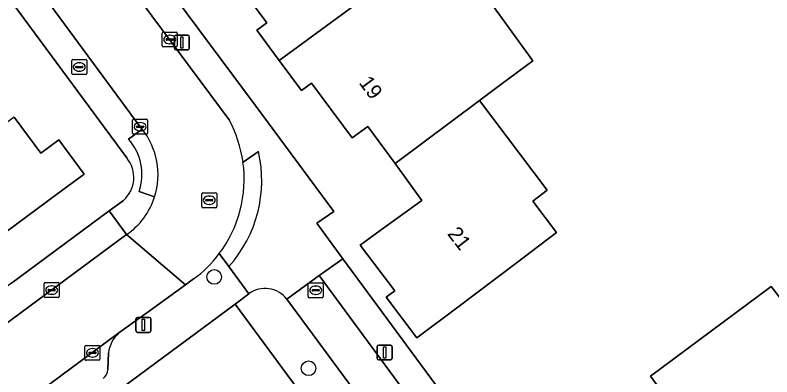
# Model space of a CAD drawing. Extents: x 163426 to 164192, y 380329 to 381641.
# Drawn here: x 163703.9 to 163754.4, y 381322.3 to 381346.5 of the extents above; entities that cross this region are included whole.
import ezdxf

# ---------------------------------------------------------------- set-up
doc = ezdxf.new("R2010")
doc.units = 0
for name, color, linetype in [('IMGEO_Boom', 7, 'Continuous'), ('IMGEO_Brandkraan', 7, 'Continuous'), ('IMGEO_Erf', 7, 'Continuous'), ('IMGEO_Fietspad_open', 7, 'Continuous'), ('IMGEO_Groenvoorziening', 7, 'Continuous'), ('IMGEO_Haag', 7, 'Continuous'), ('IMGEO_Kolk', 7, 'Continuous'), ('IMGEO_Lichtmast', 7, 'Continuous'), ('IMGEO_Pand', 7, 'Continuous'), ('IMGEO_Pand_nummerreeks', 7, 'Continuous'), ('IMGEO_Parkeervlak_open', 7, 'Continuous'), ('IMGEO_Rijbaan_lokaal_open', 7, 'Continuous'), ('IMGEO_Rioolput', 7, 'Continuous'), ('IMGEO_Voetpad_open', 7, 'Continuous')]:
    doc.layers.add(name, color=color, linetype=linetype)

msp = doc.modelspace()

# ---------------------------------------------------------------- linework, layer by layer
at = {"layer": 'IMGEO_Boom'}
for centre in [(163717.207, 381328.972), (163723.509, 381322.873)]:
    msp.add_circle(centre, 0.489, dxfattribs=at)
at = {"layer": 'IMGEO_Brandkraan'}
for p, q in [((163707.695, 381342.565), (163707.695, 381343.417)), ((163707.77, 381343.491), (163708.622, 381343.491)), ((163708.696, 381343.417), (163708.696, 381342.565)), ((163707.954, 381342.985), (163707.954, 381342.997)), ((163708.392, 381342.948), (163707.994, 381342.948)), ((163707.997, 381343.034), (163708.395, 381343.034)), ((163708.183, 381343.271), (163708.208, 381343.271)), ((163708.438, 381342.997), (163708.438, 381342.985)), ((163708.622, 381342.491), (163707.77, 381342.491)), ((163708.206, 381342.711), (163708.181, 381342.711))]:
    msp.add_line(p, q, dxfattribs=at)
for points in [[(163707.695, 381342.565), (163707.695, 381343.417)], [(163707.77, 381343.491), (163708.622, 381343.491)], [(163708.696, 381343.417), (163708.696, 381342.565)], [(163708.622, 381342.491), (163707.77, 381342.491)]]:
    msp.add_lwpolyline(points, dxfattribs=at)
for centre, radius, start, end in [((163707.772, 381343.415), 0.0765, 91.552, 178.448), ((163707.772, 381343.415), 0.0765, 91.552, 178.448), ((163708.62, 381343.415), 0.0765, 1.552, 88.448), ((163708.62, 381343.415), 0.0765, 1.552, 88.448), ((163707.994, 381342.994), 0.0403, 85.8775, 175.7526), ((163707.991, 381342.984), 0.0366, 178.938, 274.7102), ((163708.395, 381342.991), 0.043, 264.8664, 352.4533), ((163708.399, 381342.996), 0.0386, 1.7309, 96.639), ((163707.772, 381342.567), 0.0765, 181.552, 268.448), ((163707.772, 381342.567), 0.0765, 181.552, 268.448), ((163708.62, 381342.567), 0.0765, 271.552, 358.448), ((163708.62, 381342.567), 0.0765, 271.552, 358.448)]:
    msp.add_arc(centre, radius, start, end, dxfattribs=at)
for centre, major_axis, ratio, start_param, end_param in [((163708.182, 381342.991), (-0.387, 0.002), 0.722429, 4.712389, 7.853982), ((163708.207, 381342.991), (-0.39, 0.002), 0.717154, 1.570796, 4.712389)]:
    msp.add_ellipse(centre, major_axis=major_axis, ratio=ratio, start_param=start_param, end_param=end_param, dxfattribs=at)
at = {"layer": 'IMGEO_Erf'}
for points in [[(163711.368, 381336.921), (163689.653, 381366.328)], [(163735.787, 381347.111), (163738.487, 381343.396), (163736.347, 381341.821), (163734.921, 381340.756), (163739.435, 381334.761), (163738.482, 381334.044), (163740.074, 381331.931), (163737.378, 381329.902), (163733.383, 381326.894), (163730.747, 381324.909), (163728.702, 381327.626), (163729.261, 381328.047), (163726.965, 381331.096), (163728.301, 381332.068), (163731.074, 381334.085), (163729.283, 381336.545), (163727.477, 381339.027), (163726.416, 381338.255), (163723.707, 381341.921), (163723.032, 381341.423), (163721.556, 381343.421), (163720.056, 381345.451), (163720.729, 381345.949), (163718.015, 381349.623)], [(163713.908, 381348.57), (163719.936, 381340.439), (163725.188, 381333.354), (163724.056, 381332.559), (163725.803, 381330.185), (163731.664, 381322.22), (163738.793, 381312.532), (163744.754, 381316.918), (163744.079, 381317.837), (163747.519, 381320.368), (163747.706, 381320.506), (163746.336, 381322.354), (163754.409, 381328.33)], [(163754.409, 381328.33), (163756.406, 381325.749), (163759.424, 381327.984), (163761.274, 381334.469), (163761.883, 381334.26), (163762.493, 381334.701), (163765.257, 381330.885), (163769.779, 381334.233), (163768.152, 381336.451), (163770.531, 381341.026), (163772.822, 381337.902), (163777.298, 381341.215), (163776.622, 381342.131), (163780.336, 381344.88), (163784.831, 381348.208)], [(163703.839, 381339.652), (163705.619, 381337.238), (163706.83, 381338.13), (163708.53, 381335.84), (163706.775, 381334.547), (163701.911, 381330.966)], [(163703.68, 381328.564), (163710.193, 381333.382), (163711.148, 381334.089)], [(163740.553, 381295.871), (163741.259, 381296.424), (163738.778, 381299.792), (163718.602, 381327.167), (163657.027, 381281.631)]]:
    msp.add_lwpolyline(points, dxfattribs=at)
msp.add_arc((163709.799, 381335.618), 2.04, 311.4237, 39.6922, dxfattribs=at)
at = {"layer": 'IMGEO_Fietspad_open'}
msp.add_lwpolyline([(163739.99, 381303.177), (163740.117, 381303.002), (163741.174, 381301.544), (163743.348, 381303.104), (163724.224, 381329.071), (163722.053, 381327.501)], close=True, dxfattribs=at)
at = {"layer": 'IMGEO_Groenvoorziening'}
for points in [[(163719.53, 381327.853), (163718.602, 381327.167), (163738.778, 381299.792), (163739.529, 381300.378)], [(163740.117, 381303.002), (163739.99, 381303.177), (163722.053, 381327.501)]]:
    msp.add_lwpolyline(points, dxfattribs=at)
msp.add_arc((163720.61, 381326.375), 1.83, 37.9522, 126.1629, dxfattribs=at)
at = {"layer": 'IMGEO_Haag'}
for points in [[(163719.53, 381327.853), (163718.602, 381327.167), (163738.778, 381299.792), (163739.529, 381300.378)], [(163740.117, 381303.002), (163739.99, 381303.177), (163722.053, 381327.501)]]:
    msp.add_lwpolyline(points, dxfattribs=at)
msp.add_arc((163720.61, 381326.375), 1.83, 37.9522, 126.1629, dxfattribs=at)
at = {"layer": 'IMGEO_Kolk'}
for p, q in [((163713.81, 381345.329), (163714.662, 381345.329)), ((163713.735, 381344.403), (163713.735, 381345.255)), ((163713.994, 381344.823), (163713.994, 381344.835)), ((163714.037, 381344.872), (163714.435, 381344.872)), ((163714.223, 381345.109), (163714.248, 381345.109)), ((163714.478, 381344.835), (163714.478, 381344.823)), ((163714.736, 381345.255), (163714.736, 381344.403)), ((163714.662, 381344.329), (163713.81, 381344.329)), ((163714.432, 381344.786), (163714.034, 381344.786)), ((163714.246, 381344.549), (163714.221, 381344.549)), ((163711.76, 381338.579), (163711.76, 381339.431)), ((163711.835, 381339.505), (163712.687, 381339.505)), ((163712.248, 381339.285), (163712.273, 381339.285)), ((163712.761, 381339.431), (163712.761, 381338.579)), ((163712.019, 381338.999), (163712.019, 381339.011)), ((163712.457, 381338.962), (163712.059, 381338.962)), ((163712.062, 381339.048), (163712.46, 381339.048)), ((163712.503, 381339.011), (163712.503, 381338.999)), ((163712.687, 381338.505), (163711.835, 381338.505)), ((163712.271, 381338.725), (163712.246, 381338.725)), ((163705.852, 381327.671), (163705.852, 381328.523)), ((163705.927, 381328.597), (163706.779, 381328.597)), ((163706.154, 381328.14), (163706.552, 381328.14)), ((163706.34, 381328.377), (163706.365, 381328.377)), ((163706.853, 381328.523), (163706.853, 381327.671)), ((163723.488, 381327.661), (163723.488, 381328.513)), ((163723.563, 381328.587), (163724.415, 381328.587)), ((163723.79, 381328.13), (163724.188, 381328.13)), ((163723.976, 381328.367), (163724.001, 381328.367)), ((163724.489, 381328.513), (163724.489, 381327.661)), ((163706.111, 381328.091), (163706.111, 381328.103)), ((163706.549, 381328.054), (163706.151, 381328.054)), ((163706.363, 381327.817), (163706.338, 381327.817)), ((163706.595, 381328.103), (163706.595, 381328.091)), ((163723.747, 381328.081), (163723.747, 381328.093)), ((163724.185, 381328.044), (163723.787, 381328.044)), ((163723.999, 381327.807), (163723.974, 381327.807)), ((163724.231, 381328.093), (163724.231, 381328.081)), ((163706.779, 381327.597), (163705.927, 381327.597)), ((163724.415, 381327.587), (163723.563, 381327.587)), ((163708.577, 381323.48), (163708.577, 381324.332)), ((163708.652, 381324.406), (163709.504, 381324.406)), ((163709.065, 381324.186), (163709.09, 381324.186)), ((163709.578, 381324.332), (163709.578, 381323.48)), ((163708.836, 381323.9), (163708.836, 381323.912)), ((163709.274, 381323.863), (163708.876, 381323.863)), ((163708.879, 381323.949), (163709.277, 381323.949)), ((163709.088, 381323.626), (163709.063, 381323.626)), ((163709.32, 381323.912), (163709.32, 381323.9)), ((163709.504, 381323.406), (163708.652, 381323.406))]:
    msp.add_line(p, q, dxfattribs=at)
for points in [[(163713.81, 381345.329), (163714.662, 381345.329)], [(163713.735, 381344.403), (163713.735, 381345.255)], [(163714.736, 381345.255), (163714.736, 381344.403)], [(163714.662, 381344.329), (163713.81, 381344.329)], [(163711.76, 381338.579), (163711.76, 381339.431)], [(163711.835, 381339.505), (163712.687, 381339.505)], [(163712.761, 381339.431), (163712.761, 381338.579)], [(163712.687, 381338.505), (163711.835, 381338.505)], [(163705.852, 381327.671), (163705.852, 381328.523)], [(163705.927, 381328.597), (163706.779, 381328.597)], [(163706.853, 381328.523), (163706.853, 381327.671)], [(163723.488, 381327.661), (163723.488, 381328.513)], [(163723.563, 381328.587), (163724.415, 381328.587)], [(163724.489, 381328.513), (163724.489, 381327.661)], [(163706.779, 381327.597), (163705.927, 381327.597)], [(163724.415, 381327.587), (163723.563, 381327.587)], [(163708.577, 381323.48), (163708.577, 381324.332)], [(163708.652, 381324.406), (163709.504, 381324.406)], [(163709.578, 381324.332), (163709.578, 381323.48)], [(163709.504, 381323.406), (163708.652, 381323.406)]]:
    msp.add_lwpolyline(points, dxfattribs=at)
for centre, radius, start, end in [((163713.812, 381345.253), 0.0765, 91.552, 178.448), ((163713.812, 381345.253), 0.0765, 91.552, 178.448), ((163714.66, 381345.253), 0.0765, 1.552, 88.448), ((163714.66, 381345.253), 0.0765, 1.552, 88.448), ((163714.034, 381344.832), 0.0403, 85.8775, 175.7526), ((163714.031, 381344.822), 0.0366, 178.938, 274.7102), ((163714.435, 381344.829), 0.043, 264.8664, 352.4533), ((163714.439, 381344.834), 0.0386, 1.7309, 96.639), ((163713.812, 381344.405), 0.0765, 181.552, 268.448), ((163713.812, 381344.405), 0.0765, 181.552, 268.448), ((163714.66, 381344.405), 0.0765, 271.552, 358.448), ((163714.66, 381344.405), 0.0765, 271.552, 358.448), ((163711.837, 381339.429), 0.0765, 91.552, 178.448), ((163711.837, 381339.429), 0.0765, 91.552, 178.448), ((163712.685, 381339.429), 0.0765, 1.552, 88.448), ((163712.685, 381339.429), 0.0765, 1.552, 88.448), ((163712.059, 381339.008), 0.0403, 85.8775, 175.7526), ((163712.056, 381338.998), 0.0366, 178.938, 274.7102), ((163712.46, 381339.005), 0.043, 264.8664, 352.4533), ((163712.464, 381339.01), 0.0386, 1.7309, 96.639), ((163711.837, 381338.581), 0.0765, 181.552, 268.448), ((163711.837, 381338.581), 0.0765, 181.552, 268.448), ((163712.685, 381338.581), 0.0765, 271.552, 358.448), ((163712.685, 381338.581), 0.0765, 271.552, 358.448), ((163705.929, 381328.521), 0.0765, 91.552, 178.448), ((163705.929, 381328.521), 0.0765, 91.552, 178.448), ((163706.151, 381328.1), 0.0403, 85.8775, 175.7526), ((163706.556, 381328.102), 0.0386, 1.7309, 96.639), ((163706.777, 381328.521), 0.0765, 1.552, 88.448), ((163706.777, 381328.521), 0.0765, 1.552, 88.448), ((163723.565, 381328.511), 0.0765, 91.552, 178.448), ((163723.565, 381328.511), 0.0765, 91.552, 178.448), ((163723.787, 381328.09), 0.0403, 85.8775, 175.7526), ((163724.192, 381328.092), 0.0386, 1.7309, 96.639), ((163724.413, 381328.511), 0.0765, 1.552, 88.448), ((163724.413, 381328.511), 0.0765, 1.552, 88.448), ((163705.929, 381327.673), 0.0765, 181.552, 268.448), ((163705.929, 381327.673), 0.0765, 181.552, 268.448), ((163706.148, 381328.09), 0.0366, 178.938, 274.7102), ((163706.552, 381328.097), 0.043, 264.8664, 352.4533), ((163706.777, 381327.673), 0.0765, 271.552, 358.448), ((163706.777, 381327.673), 0.0765, 271.552, 358.448), ((163723.565, 381327.663), 0.0765, 181.552, 268.448), ((163723.565, 381327.663), 0.0765, 181.552, 268.448), ((163723.784, 381328.08), 0.0366, 178.938, 274.7102), ((163724.188, 381328.087), 0.043, 264.8664, 352.4533), ((163724.413, 381327.663), 0.0765, 271.552, 358.448), ((163724.413, 381327.663), 0.0765, 271.552, 358.448), ((163708.654, 381324.33), 0.0765, 91.552, 178.448), ((163708.654, 381324.33), 0.0765, 91.552, 178.448), ((163709.502, 381324.33), 0.0765, 1.552, 88.448), ((163709.502, 381324.33), 0.0765, 1.552, 88.448), ((163708.876, 381323.909), 0.0403, 85.8775, 175.7526), ((163708.873, 381323.899), 0.0366, 178.938, 274.7102), ((163709.277, 381323.906), 0.043, 264.8664, 352.4533), ((163709.281, 381323.911), 0.0386, 1.7309, 96.639), ((163708.654, 381323.482), 0.0765, 181.552, 268.448), ((163708.654, 381323.482), 0.0765, 181.552, 268.448), ((163709.502, 381323.482), 0.0765, 271.552, 358.448), ((163709.502, 381323.482), 0.0765, 271.552, 358.448)]:
    msp.add_arc(centre, radius, start, end, dxfattribs=at)
for centre, major_axis, ratio, start_param, end_param in [((163714.222, 381344.829), (-0.387, 0.002), 0.722429, 4.712389, 7.853982), ((163714.247, 381344.829), (-0.39, 0.002), 0.717154, 1.570796, 4.712389), ((163712.247, 381339.005), (-0.387, 0.002), 0.722429, 4.712389, 7.853982), ((163712.272, 381339.005), (-0.39, 0.002), 0.717154, 1.570796, 4.712389), ((163706.339, 381328.097), (-0.387, 0.002), 0.722429, 4.712389, 7.853982), ((163706.364, 381328.097), (-0.39, 0.002), 0.717154, 1.570796, 4.712389), ((163723.975, 381328.087), (-0.387, 0.002), 0.722429, 4.712389, 7.853982), ((163724, 381328.087), (-0.39, 0.002), 0.717154, 1.570796, 4.712389), ((163709.064, 381323.906), (-0.387, 0.002), 0.722429, 4.712389, 7.853982), ((163709.089, 381323.906), (-0.39, 0.002), 0.717154, 1.570796, 4.712389)]:
    msp.add_ellipse(centre, major_axis=major_axis, ratio=ratio, start_param=start_param, end_param=end_param, dxfattribs=at)
at = {"layer": 'IMGEO_Lichtmast'}
for p, q in [((163714.551, 381344.228), (163714.551, 381345.028)), ((163714.551, 381345.028), (163714.551, 381344.228)), ((163714.651, 381345.128), (163715.441, 381345.128)), ((163715.441, 381345.128), (163714.651, 381345.128)), ((163715.541, 381345.028), (163715.541, 381344.228)), ((163715.541, 381344.228), (163715.541, 381345.028)), ((163715.441, 381344.128), (163714.651, 381344.128)), ((163714.651, 381344.128), (163715.441, 381344.128)), ((163711.984, 381325.369), (163711.984, 381326.169)), ((163711.984, 381326.169), (163711.984, 381325.369)), ((163712.084, 381326.269), (163712.874, 381326.269)), ((163712.874, 381326.269), (163712.084, 381326.269)), ((163712.974, 381326.169), (163712.974, 381325.369)), ((163712.974, 381325.369), (163712.974, 381326.169)), ((163712.874, 381325.269), (163712.084, 381325.269)), ((163712.084, 381325.269), (163712.874, 381325.269)), ((163728.094, 381323.528), (163728.094, 381324.328)), ((163728.094, 381324.328), (163728.094, 381323.528)), ((163728.194, 381324.428), (163728.984, 381324.428)), ((163728.984, 381324.428), (163728.194, 381324.428)), ((163729.084, 381324.328), (163729.084, 381323.528)), ((163729.084, 381323.528), (163729.084, 381324.328)), ((163728.984, 381323.428), (163728.194, 381323.428)), ((163728.194, 381323.428), (163728.984, 381323.428))]:
    msp.add_line(p, q, dxfattribs=at)
for points in [[(163714.971, 381345.003), (163715.121, 381345.003), (163715.121, 381344.253), (163714.971, 381344.253), (163714.971, 381345.003)], [(163712.404, 381326.144), (163712.554, 381326.144), (163712.554, 381325.394), (163712.404, 381325.394), (163712.404, 381326.144)], [(163728.514, 381324.303), (163728.664, 381324.303), (163728.664, 381323.553), (163728.514, 381323.553), (163728.514, 381324.303)]]:
    msp.add_lwpolyline(points, dxfattribs=at)
for centre, start, end in [((163714.651, 381345.028), 90, 180), ((163714.651, 381345.028), 90, 180), ((163715.441, 381345.028), 0, 90), ((163715.441, 381345.028), 360, 90), ((163714.651, 381344.228), 180, 270), ((163714.651, 381344.228), 180, 270), ((163715.441, 381344.228), 270, 0), ((163715.441, 381344.228), 270, 0), ((163712.084, 381326.169), 90, 180), ((163712.084, 381326.169), 90, 180), ((163712.874, 381326.169), 0, 90), ((163712.874, 381326.169), 360, 90), ((163712.084, 381325.369), 180, 270), ((163712.084, 381325.369), 180, 270), ((163712.874, 381325.369), 270, 0), ((163712.874, 381325.369), 270, 0), ((163728.194, 381324.328), 90, 180), ((163728.194, 381324.328), 90, 180), ((163728.984, 381324.328), 0, 90), ((163728.984, 381324.328), 360, 90), ((163728.194, 381323.528), 180, 270), ((163728.194, 381323.528), 180, 270), ((163728.984, 381323.528), 270, 0), ((163728.984, 381323.528), 270, 0)]:
    msp.add_arc(centre, 0.1, start, end, dxfattribs=at)
at = {"layer": 'IMGEO_Pand'}
for points in [[(163721.556, 381343.421), (163729.777, 381349.473), (163727.101, 381353.026), (163726.346, 381352.457), (163724.754, 381354.571), (163723.991, 381354.011), (163723.636, 381354.492), (163721.821, 381353.159), (163722.175, 381352.677), (163718.015, 381349.623), (163720.729, 381345.949), (163720.056, 381345.451)], [(163735.787, 381347.111), (163732.547, 381351.512), (163729.777, 381349.473), (163721.556, 381343.421), (163723.032, 381341.423), (163723.707, 381341.921), (163726.416, 381338.255), (163727.477, 381339.027), (163729.283, 381336.545), (163734.921, 381340.756), (163736.347, 381341.821), (163738.487, 381343.396)], [(163734.921, 381340.756), (163729.283, 381336.545), (163731.074, 381334.085), (163728.301, 381332.068), (163726.965, 381331.096), (163729.261, 381328.047), (163728.702, 381327.626), (163730.747, 381324.909), (163733.383, 381326.894), (163737.378, 381329.902), (163740.074, 381331.931), (163738.482, 381334.044), (163739.435, 381334.761)], [(163696.592, 381334.313), (163697.097, 381333.631), (163700.07, 381329.61), (163701.911, 381330.966), (163706.775, 381334.547), (163708.53, 381335.84), (163706.83, 381338.13), (163705.619, 381337.238), (163703.839, 381339.652)], [(163756.406, 381325.749), (163754.409, 381328.33), (163746.336, 381322.354), (163747.706, 381320.506), (163753.793, 381312.296), (163755.819, 381313.784), (163755.286, 381314.463), (163758.925, 381317.163), (163758.165, 381318.209), (163760.639, 381320.005)]]:
    msp.add_lwpolyline(points, close=True, dxfattribs=at)
at = {"layer": 'IMGEO_Parkeervlak_open'}
for points in [[(163710.833, 381325.231), (163656.677, 381285.107)], [(163710.107, 381322.8), (163710.147, 381323.915)]]:
    msp.add_lwpolyline(points, dxfattribs=at)
for centre, radius, start, end in [((163712.269, 381323.646), 2.139, 132.1696, 172.7664), ((163709.322, 381322.83), 0.786, 306.6553, 357.7962)]:
    msp.add_arc(centre, radius, start, end, dxfattribs=at)
at = {"layer": 'IMGEO_Rijbaan_lokaal_open'}
for points in [[(163691.302, 381367.414), (163695.359, 381361.911), (163701.623, 381353.484), (163705.653, 381347.998), (163712.258, 381339.005), (163712.395, 381338.84)], [(163718.204, 381339.455), (163712.407, 381347.279)], [(163656.677, 381285.107), (163710.833, 381325.231), (163712.71, 381326.586), (163715.289, 381328.447), (163711.359, 381331.806), (163694.161, 381319.1), (163691.113, 381316.849), (163682.665, 381310.607), (163677.183, 381306.556), (163668.338, 381300.021), (163662.864, 381295.976), (163653.949, 381289.389), (163650.902, 381287.137), (163650.108, 381286.551)], [(163711.359, 381331.806), (163715.289, 381328.447), (163715.832, 381328.839)]]:
    msp.add_lwpolyline(points, dxfattribs=at)
for centre, radius, start, end in [((163710.95, 381335.511), 8.257, 7.8143, 28.5308), ((163708.561, 381335.799), 4.894, 342.3838, 38.4176), ((163710.938, 381335.506), 8.269, 322.9972, 7.842), ((163708.641, 381335.774), 4.81, 304.4097, 342.3778), ((163710.972, 381335.466), 8.218, 306.2522, 323.0738)]:
    msp.add_arc(centre, radius, start, end, dxfattribs=at)
at = {"layer": 'IMGEO_Rioolput'}
for p, q in [((163716.376, 381333.672), (163716.376, 381334.524)), ((163716.451, 381334.598), (163717.303, 381334.598)), ((163716.864, 381334.378), (163716.889, 381334.378)), ((163717.377, 381334.524), (163717.377, 381333.672)), ((163716.635, 381334.092), (163716.635, 381334.104)), ((163717.073, 381334.055), (163716.675, 381334.055)), ((163716.678, 381334.141), (163717.076, 381334.141)), ((163716.887, 381333.818), (163716.862, 381333.818)), ((163717.119, 381334.104), (163717.119, 381334.092)), ((163717.303, 381333.598), (163716.451, 381333.598))]:
    msp.add_line(p, q, dxfattribs=at)
for points in [[(163716.376, 381333.672), (163716.376, 381334.524)], [(163716.451, 381334.598), (163717.303, 381334.598)], [(163717.377, 381334.524), (163717.377, 381333.672)], [(163717.303, 381333.598), (163716.451, 381333.598)]]:
    msp.add_lwpolyline(points, dxfattribs=at)
for centre, radius, start, end in [((163716.453, 381334.522), 0.0765, 91.552, 178.448), ((163716.453, 381334.522), 0.0765, 91.552, 178.448), ((163717.301, 381334.522), 0.0765, 1.552, 88.448), ((163717.301, 381334.522), 0.0765, 1.552, 88.448), ((163716.675, 381334.101), 0.0403, 85.8775, 175.7526), ((163716.672, 381334.091), 0.0366, 178.938, 274.7102), ((163717.076, 381334.098), 0.043, 264.8664, 352.4533), ((163717.08, 381334.103), 0.0386, 1.7309, 96.639), ((163716.453, 381333.674), 0.0765, 181.552, 268.448), ((163716.453, 381333.674), 0.0765, 181.552, 268.448), ((163717.301, 381333.674), 0.0765, 271.552, 358.448), ((163717.301, 381333.674), 0.0765, 271.552, 358.448)]:
    msp.add_arc(centre, radius, start, end, dxfattribs=at)
for centre, major_axis, ratio, start_param, end_param in [((163716.863, 381334.098), (-0.387, 0.002), 0.722429, 4.712389, 7.853982), ((163716.888, 381334.098), (-0.39, 0.002), 0.717154, 1.570796, 4.712389)]:
    msp.add_ellipse(centre, major_axis=major_axis, ratio=ratio, start_param=start_param, end_param=end_param, dxfattribs=at)
at = {"layer": 'IMGEO_Voetpad_open'}
for points in [[(163711.492, 381338.181), (163712.395, 381338.84), (163712.258, 381339.005), (163705.653, 381347.998), (163701.623, 381353.484), (163695.359, 381361.911), (163691.302, 381367.414)], [(163689.653, 381366.328), (163711.368, 381336.921)], [(163724.056, 381332.559), (163725.188, 381333.354), (163719.936, 381340.439), (163713.908, 381348.57), (163713.489, 381348.963), (163711.445, 381352.242)], [(163712.407, 381347.279), (163718.204, 381339.455)], [(163712.395, 381338.84), (163711.492, 381338.181)], [(163720.159, 381337.356), (163719.13, 381336.634)], [(163719.13, 381336.634), (163720.159, 381337.356)], [(163712.197, 381334.675), (163713.225, 381334.318)], [(163713.225, 381334.318), (163712.197, 381334.675)], [(163711.148, 381334.089), (163710.193, 381333.382), (163711.359, 381331.806)], [(163722.053, 381327.501), (163724.224, 381329.071), (163725.803, 381330.185), (163724.056, 381332.559)], [(163717.542, 381330.529), (163718.193, 381329.68)], [(163718.602, 381327.167), (163719.53, 381327.853), (163718.193, 381329.68), (163717.542, 381330.529)], [(163745.605, 381303.274), (163742.918, 381306.926), (163738.793, 381312.532), (163731.664, 381322.22), (163725.803, 381330.185), (163724.224, 381329.071), (163743.348, 381303.104), (163741.174, 381301.544), (163740.117, 381303.002)], [(163718.193, 381329.68), (163719.53, 381327.853)], [(163715.832, 381328.839), (163715.289, 381328.447), (163712.71, 381326.586), (163710.833, 381325.231)], [(163657.027, 381281.631), (163718.602, 381327.167)], [(163710.147, 381323.915), (163710.107, 381322.8)]]:
    msp.add_lwpolyline(points, dxfattribs=at)
msp.add_lwpolyline([(163682.665, 381310.607), (163691.113, 381316.849), (163694.161, 381319.1), (163711.359, 381331.806), (163710.193, 381333.382), (163703.68, 381328.564), (163692.92, 381320.603), (163649.769, 381288.678), (163650.902, 381287.137), (163653.949, 381289.389), (163662.864, 381295.976), (163668.338, 381300.021), (163677.183, 381306.556)], close=True, dxfattribs=at)
for centre, radius, start, end in [((163710.95, 381335.511), 8.257, 7.8143, 28.5308), ((163708.561, 381335.799), 4.894, 342.3838, 38.4176), ((163708.784, 381335.813), 3.597, 341.5635, 41.1758), ((163708.784, 381335.813), 3.597, 341.5635, 41.1758), ((163711.784, 381335.411), 8.598, 318.1946, 13.0735), ((163711.784, 381335.411), 8.598, 318.1946, 13.0735), ((163709.799, 381335.618), 2.04, 311.4237, 39.6922), ((163710.938, 381335.506), 8.269, 322.9972, 7.842), ((163708.641, 381335.774), 4.81, 304.4097, 342.3778), ((163710.972, 381335.466), 8.218, 306.2522, 323.0738), ((163720.61, 381326.375), 1.83, 37.9522, 126.1629), ((163712.269, 381323.646), 2.139, 132.1696, 172.7664), ((163709.322, 381322.83), 0.786, 306.6553, 357.7962)]:
    msp.add_arc(centre, radius, start, end, dxfattribs=at)

# ---------------------------------------------------------------- texts
at = {"layer": 'IMGEO_Pand_nummerreeks'}
for s, rotation, p in [('19', 306.4628, (163726.831, 381341.935)), ('21', 307.8387, (163732.735, 381331.838))]:
    msp.add_text(s, height=1, rotation=rotation, dxfattribs=at).set_placement(p)

doc.saveas('drawing.dxf')
